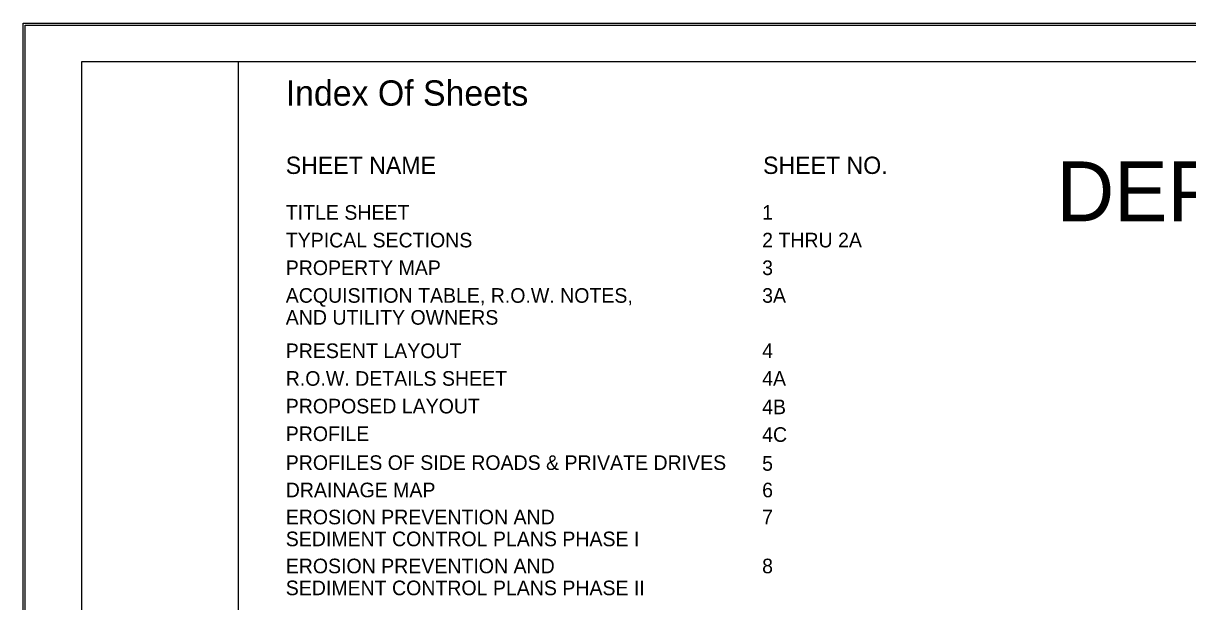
# Model space of a CAD drawing. Extents: x 1577619 to 1828281, y 483481 to 598136.
# Drawn here: x 1647461 to 1672781, y 527639 to 540205 of the extents above; entities that cross this region are included whole.
import ezdxf

# ---------------------------------------------------------------- set-up
doc = ezdxf.new("R2010")
doc.units = 0
for name, color, linetype in [('DESIGN - SHEET - Corner Text', 7, 'Continuous'), ('DESIGN - SHEET - Linework', 7, 'Continuous'), ('DESIGN - SHEET - Plot Shape', 7, 'Continuous')]:
    doc.layers.add(name, color=color, linetype=linetype)

msp = doc.modelspace()

# ---------------------------------------------------------------- linework, layer by layer
at = {"layer": 'DESIGN - SHEET - Linework'}
for p, q in [((1647461, 540205), (1715541, 540205)), ((1647461, 496549), (1647461, 540205))]:
    msp.add_line(p, q, dxfattribs=at)
msp.add_lwpolyline([(1652139, 539377), (1715107, 539377), (1715107, 497377), (1652139, 497377), (1652139, 539377)], dxfattribs=at)
at = {"layer": 'DESIGN - SHEET - Plot Shape'}
for points in [[(1647501, 540165), (1715501, 540165), (1715501, 496589), (1647501, 496589)], [(1648737, 539377), (1715107, 539377), (1715107, 497377), (1648737, 497377)]]:
    msp.add_lwpolyline(points, close=True, dxfattribs=at)

# ---------------------------------------------------------------- texts
at = {"layer": 'DESIGN - SHEET - Corner Text'}
for s, height, p in [('Index Of Sheets', 550, (1653168, 538415)), ('SHEET NAME', 375.8, (1653168, 536932)), ('SHEET NO.', 375.8, (1663547, 536932)), ('DEPARTMENT OF TRANSPORTATION', 1300, (1669928, 535904)), ('TITLE SHEET', 317.43, (1653168, 535937)), ('1', 317, (1663527, 535937)), ('TYPICAL SECTIONS', 317.43, (1653168, 535336)), ('2 THRU 2A', 317.4, (1663527, 535336)), ('PROPERTY MAP', 317.43, (1653168, 534735)), ('3 ', 317.4, (1663527, 534735)), ('ACQUISITION TABLE, R.O.W. NOTES, ', 317.43, (1653168, 534133)), ('3A', 317.4, (1663527, 534133)), ('AND UTILITY OWNERS', 317.43, (1653168, 533657)), ('PRESENT LAYOUT', 317.43, (1653168, 532931)), ('4 ', 317.4, (1663527, 532931)), ('R.O.W. DETAILS SHEET', 317.43, (1653168, 532330)), ('4A', 317.4, (1663527, 532330)), ('PROPOSED LAYOUT', 317.43, (1653168, 531729)), ('4B', 317.4, (1663527, 531712)), ('PROFILE', 317.4, (1653168, 531128)), ('4C', 317.4, (1663527, 531111)), ('PROFILES OF SIDE ROADS & PRIVATE DRIVES', 317.43, (1653168, 530501)), ('5', 317, (1663527, 530484)), ('DRAINAGE MAP', 317.43, (1653168, 529907)), ('6', 317, (1663527, 529907)), ('EROSION PREVENTION AND ', 317.43, (1653168, 529320)), ('7', 317, (1663527, 529320)), ('SEDIMENT CONTROL PLANS PHASE I', 317.43, (1653168, 528844)), ('EROSION PREVENTION AND ', 317.43, (1653168, 528256)), ('8', 317, (1663527, 528256)), ('SEDIMENT CONTROL PLANS PHASE II', 317.43, (1653168, 527780))]:
    msp.add_text(s, height=height, dxfattribs=at).set_placement(p)

doc.saveas('drawing.dxf')
